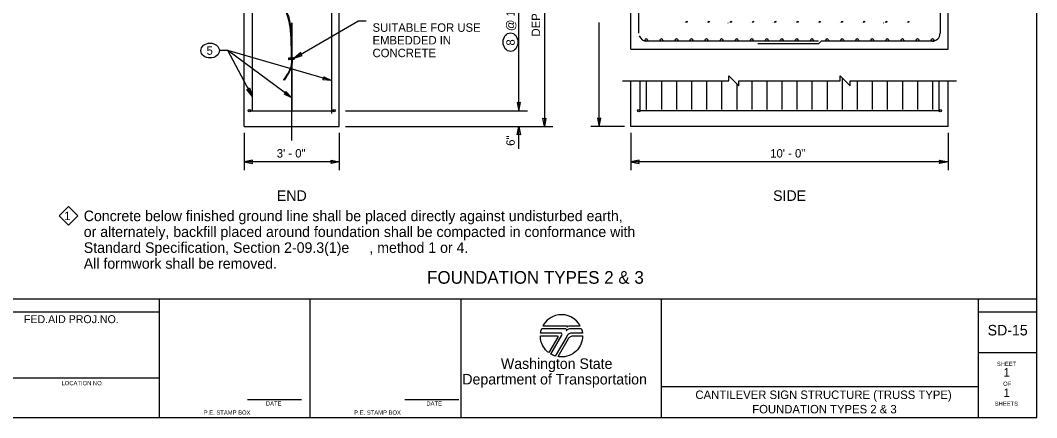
# Model space of a CAD drawing. Extents: x 99862 to 103151, y 100000 to 102076.
# Drawn here: x 101227 to 103150, y 100000 to 100752 of the extents above; entities that cross this region are included whole.
import ezdxf

# ---------------------------------------------------------------- set-up
doc = ezdxf.new("R2010")
doc.units = 0
for name, color, linetype in [('Level 10', 7, 'Continuous'), ('Level 12', 7, 'Continuous'), ('Level 15', 7, 'Continuous'), ('Level 2', 7, 'Continuous'), ('Level 20', 7, 'Continuous'), ('Level 23', 7, 'Continuous'), ('Level 60', 7, 'Continuous'), ('Level 62', 7, 'Continuous'), ('Level 7', 7, 'Continuous')]:
    doc.layers.add(name, color=color, linetype=linetype)

msp = doc.modelspace()

# ---------------------------------------------------------------- linework, layer by layer
at = {"layer": 'Level 10'}
for p, q in [((101665.3, 101195.7), (101665.3, 100580.7)), ((101665.3, 101195.7), (101665.3, 100580.7)), ((101815.3, 101195.7), (101815.3, 100575.4)), ((102397.2, 100727), (102397.2, 100847)), ((102967.2, 100847), (102967.2, 100727)), ((101740.3, 100747.1), (101740.3, 100700.8)), ((101740.3, 100747.1), (101740.3, 100700.8)), ((102737.2, 100712), (102412.2, 100712)), ((102737.2, 100707), (102622.2, 100707)), ((102742.2, 100712), (102737.2, 100707)), ((102952.2, 100712), (102742.2, 100712)), ((101740.3, 100667.4), (101740.3, 100580.7)), ((101740.3, 100667.4), (101740.3, 100580.7)), ((102399.4, 100583.2), (102399.4, 100637)), ((102399.4, 100583.2), (102399.4, 100637)), ((102411.3, 100637), (102411.3, 100583.2)), ((102411.3, 100637), (102411.3, 100583.2)), ((102439.8, 100637), (102439.8, 100583.2)), ((102439.8, 100637), (102439.8, 100583.2)), ((102468.3, 100637), (102468.3, 100583.2)), ((102468.3, 100637), (102468.3, 100583.2)), ((102496.8, 100637), (102496.8, 100583.2)), ((102496.8, 100637), (102496.8, 100583.2)), ((102525.3, 100637), (102525.3, 100583.2)), ((102525.3, 100637), (102525.3, 100583.2)), ((102553.8, 100637), (102553.8, 100583.2)), ((102553.8, 100637), (102553.8, 100583.2)), ((102582.3, 100631.5), (102582.3, 100583.2)), ((102582.3, 100631.5), (102582.3, 100583.2)), ((102610.8, 100637), (102610.8, 100583.2)), ((102610.8, 100637), (102610.8, 100583.2)), ((102639.3, 100637), (102639.3, 100583.2)), ((102639.3, 100637), (102639.3, 100583.2)), ((102667.8, 100637), (102667.8, 100583.2)), ((102667.8, 100637), (102667.8, 100583.2)), ((102696.3, 100637), (102696.3, 100583.2)), ((102696.3, 100637), (102696.3, 100583.2)), ((102724.8, 100637), (102724.8, 100583.2)), ((102724.8, 100637), (102724.8, 100583.2)), ((102753.3, 100637), (102753.3, 100583.2)), ((102753.3, 100637), (102753.3, 100583.2)), ((102781.8, 100642.7), (102781.8, 100583.2)), ((102781.8, 100642.7), (102781.8, 100583.2)), ((102810.3, 100637), (102810.3, 100583.2)), ((102810.3, 100637), (102810.3, 100583.2)), ((102838.8, 100637), (102838.8, 100583.2)), ((102838.8, 100637), (102838.8, 100583.2)), ((102867.3, 100637), (102867.3, 100583.2)), ((102867.3, 100637), (102867.3, 100583.2)), ((102895.8, 100637), (102895.8, 100583.2)), ((102895.8, 100637), (102895.8, 100583.2)), ((102924.3, 100637), (102924.3, 100583.2)), ((102924.3, 100637), (102924.3, 100583.2)), ((102952.8, 100637), (102952.8, 100583.2)), ((102952.8, 100637), (102952.8, 100583.2)), ((102965, 100637), (102965, 100583.2)), ((101660.3, 100580.7), (101820.3, 100580.7)), ((101660.3, 100580.7), (101820.3, 100580.7)), ((102967.2, 100580.7), (102397.2, 100580.7))]:
    msp.add_line(p, q, dxfattribs=at)
for centre in [(102411.3, 100714.5), (102411.3, 100714.5), (102439.8, 100714.5), (102439.8, 100714.5), (102468.3, 100714.5), (102468.3, 100714.5), (102496.8, 100714.5), (102496.8, 100714.5), (102525.3, 100714.5), (102525.3, 100714.5), (102553.8, 100714.5), (102553.8, 100714.5), (102582.3, 100714.5), (102582.3, 100714.5), (102610.8, 100714.5), (102610.8, 100714.5), (102639.3, 100714.5), (102639.3, 100714.5), (102667.8, 100714.5), (102667.8, 100714.5), (102696.3, 100714.5), (102696.3, 100714.5), (102724.8, 100714.5), (102724.8, 100714.5), (102753.3, 100714.5), (102753.3, 100714.5), (102781.8, 100714.5), (102781.8, 100714.5), (102810.3, 100714.5), (102810.3, 100714.5), (102838.8, 100714.5), (102838.8, 100714.5), (102867.3, 100714.5), (102867.3, 100714.5), (102895.8, 100714.5), (102895.8, 100714.5), (102924.3, 100714.5), (102924.3, 100714.5), (102952.8, 100714.5), (102952.8, 100714.5), (101660.3, 100580.7), (101660.3, 100580.7), (101820.3, 100580.7), (101820.3, 100580.7), (102397.2, 100580.7), (102397.2, 100580.7), (102967.2, 100580.7), (102967.2, 100580.7)]:
    msp.add_circle(centre, 2.5, dxfattribs=at)
for centre, start, end in [((102952.2, 100727), 270, 0), ((102412.2, 100727), 197.2697, 270.4082)]:
    msp.add_arc(centre, 15, start, end, dxfattribs=at)
at = {"layer": 'Level 12'}
for p, q in [((101736, 100751.4), (101735, 100750)), ((101736, 100751.4), (101735, 100750)), ((101735.6, 100746.8), (101736.7, 100748.1)), ((101735.6, 100746.8), (101736.7, 100748.1)), ((101738.8, 100731.7), (101737.6, 100730.5)), ((101738.8, 100731.7), (101737.6, 100730.5)), ((101737.8, 100727.2), (101739, 100728.4)), ((101737.8, 100727.2), (101739, 100728.4)), ((101739.9, 100713.4), (101738.6, 100712.2)), ((101739.9, 100713.4), (101738.6, 100712.2)), ((101738.7, 100708.9), (101740, 100710)), ((101738.7, 100708.9), (101740, 100710)), ((101740.5, 100692.5), (101739.2, 100691.4)), ((101740.5, 100692.5), (101739.2, 100691.4)), ((101739.3, 100688.1), (101740.6, 100689.2)), ((101739.3, 100688.1), (101740.6, 100689.2)), ((101735.8, 100658), (101737.4, 100658.5)), ((101735.8, 100658), (101737.4, 100658.5)), ((101738.6, 100661.6), (101737, 100661)), ((101738.6, 100661.6), (101737, 100661)), ((101726.4, 100641.6), (101728.1, 100641.9)), ((101726.4, 100641.6), (101728.1, 100641.9)), ((101730, 100644.6), (101728.3, 100644.4)), ((101730, 100644.6), (101728.3, 100644.4))]:
    msp.add_line(p, q, dxfattribs=at)
for points in [[(101736, 100751.4), (101736, 100751.4)], [(101736, 100751.4), (101736, 100751.4)], [(101736.7, 100748.1), (101736.7, 100748.1)], [(101736.7, 100748.1), (101736.7, 100748.1)], [(101738.8, 100731.7), (101738.8, 100731.7)], [(101738.8, 100731.7), (101738.8, 100731.7)], [(101739, 100728.4), (101739, 100728.4)], [(101739, 100728.4), (101739, 100728.4)], [(101739.9, 100713.4), (101739.9, 100713.4)], [(101739.9, 100713.4), (101739.9, 100713.4)], [(101740, 100710), (101740, 100710)], [(101740, 100710), (101740, 100710)], [(101740.5, 100692.5), (101740.5, 100692.5)], [(101740.5, 100692.5), (101740.5, 100692.5)], [(101740.6, 100689.2), (101740.6, 100689.2)], [(101740.6, 100689.2), (101740.6, 100689.2)], [(101737.4, 100658.5), (101737.4, 100658.5)], [(101737.4, 100658.5), (101737.4, 100658.5)], [(101738.6, 100661.6), (101738.6, 100661.6)], [(101738.6, 100661.6), (101738.6, 100661.6)], [(101728.1, 100641.9), (101728.1, 100641.9)], [(101728.1, 100641.9), (101728.1, 100641.9)], [(101730, 100644.6), (101730, 100644.6)], [(101730, 100644.6), (101730, 100644.6)]]:
    msp.add_lwpolyline(points, dxfattribs=at)
for points in [[(101735, 100750), (101735.2, 100748.9), (101735.4, 100747.8), (101735.6, 100746.8)], [(101735, 100750), (101735.2, 100748.9), (101735.4, 100747.8), (101735.6, 100746.8)], [(101736.7, 100748.1), (101736.4, 100749.2), (101736.2, 100750.3), (101736, 100751.4)], [(101736.7, 100748.1), (101736.4, 100749.2), (101736.2, 100750.3), (101736, 100751.4)], [(101737.6, 100730.5), (101737.6, 100729.4), (101737.7, 100728.3), (101737.8, 100727.2)], [(101737.6, 100730.5), (101737.6, 100729.4), (101737.7, 100728.3), (101737.8, 100727.2)], [(101739, 100728.4), (101738.9, 100729.5), (101738.8, 100730.6), (101738.8, 100731.7)], [(101739, 100728.4), (101738.9, 100729.5), (101738.8, 100730.6), (101738.8, 100731.7)], [(101738.6, 100712.2), (101738.7, 100711.1), (101738.7, 100710), (101738.7, 100708.9)], [(101738.6, 100712.2), (101738.7, 100711.1), (101738.7, 100710), (101738.7, 100708.9)], [(101740, 100710), (101739.9, 100711.1), (101739.9, 100712.2), (101739.9, 100713.4)], [(101740, 100710), (101739.9, 100711.1), (101739.9, 100712.2), (101739.9, 100713.4)], [(101739.2, 100691.4), (101739.3, 100690.3), (101739.3, 100689.2), (101739.3, 100688.1)], [(101739.2, 100691.4), (101739.3, 100690.3), (101739.3, 100689.2), (101739.3, 100688.1)], [(101740.6, 100689.2), (101740.5, 100690.3), (101740.5, 100691.4), (101740.5, 100692.5)], [(101740.6, 100689.2), (101740.5, 100690.3), (101740.5, 100691.4), (101740.5, 100692.5)], [(101737, 100661), (101736.6, 100660), (101736.2, 100659), (101735.8, 100658)], [(101737, 100661), (101736.6, 100660), (101736.2, 100659), (101735.8, 100658)], [(101737.4, 100658.5), (101737.8, 100659.6), (101738.2, 100660.6), (101738.6, 100661.6)], [(101737.4, 100658.5), (101737.8, 100659.6), (101738.2, 100660.6), (101738.6, 100661.6)], [(101728.3, 100644.4), (101727.7, 100643.5), (101727.1, 100642.6), (101726.4, 100641.6)], [(101728.3, 100644.4), (101727.7, 100643.5), (101727.1, 100642.6), (101726.4, 100641.6)], [(101728.1, 100641.9), (101728.7, 100642.8), (101729.4, 100643.7), (101730, 100644.6)], [(101728.1, 100641.9), (101728.7, 100642.8), (101729.4, 100643.7), (101730, 100644.6)]]:
    msp.add_open_spline(points, degree=2, dxfattribs=at)
at = {"layer": 'Level 15'}
for p, q in [((102218.3, 101150.7), (102218.3, 100550.7)), ((102218.3, 101150.7), (102218.3, 100550.7)), ((102170.3, 100580.7), (102170.3, 101110.7)), ((102170.3, 100580.7), (102170.3, 101110.7)), ((101740.3, 100667.4), (101740.3, 100747.1)), ((101740.3, 100667.4), (101740.3, 100747.1)), ((101745.1, 100680), (101865.2, 100749.9)), ((101881.2, 100749.9), (101865.2, 100749.9)), ((101881.2, 100749.9), (101865.2, 100749.9)), ((102322.2, 100550.7), (102322.2, 100747.7)), ((101619.3, 100694.4), (101603.3, 100694.4)), ((101619.3, 100694.4), (101603.3, 100694.4)), ((101665.3, 100608.4), (101619.3, 100694.4)), ((101740.3, 100605.2), (101619.3, 100694.4)), ((101815.3, 100637.6), (101619.3, 100694.4)), ((101665.3, 100608.4), (101619.3, 100694.4)), ((101740.3, 100605.2), (101619.3, 100694.4)), ((101740.3, 100524), (101740.3, 100667.4)), ((101740.3, 100524), (101740.3, 100667.4)), ((102366.2, 100637), (102567.5, 100637)), ((102567.5, 100637), (102567.5, 100646.3)), ((102567.5, 100646.3), (102586.1, 100627.7)), ((102567.5, 100637), (102567.5, 100646.3)), ((102567.5, 100646.3), (102586.1, 100627.7)), ((102586.1, 100627.7), (102586.1, 100637)), ((102586.1, 100637), (102778.2, 100637)), ((102586.1, 100627.7), (102586.1, 100637)), ((102586.1, 100637), (102778.2, 100637)), ((102778.2, 100637), (102778.2, 100646.3)), ((102778.2, 100646.3), (102796.8, 100627.7)), ((102778.2, 100637), (102778.2, 100646.3)), ((102778.2, 100646.3), (102796.8, 100627.7)), ((102796.8, 100627.7), (102796.8, 100637)), ((102796.8, 100637), (102998.2, 100637)), ((102796.8, 100627.7), (102796.8, 100637)), ((101842.3, 100580.7), (102186.3, 100580.7)), ((101842.3, 100580.7), (102186.3, 100580.7)), ((101650.3, 100538.7), (101650.3, 100468)), ((101650.3, 100538.7), (101650.3, 100468)), ((101830.3, 100538.7), (101830.3, 100468)), ((101830.3, 100538.7), (101830.3, 100468)), ((101842.3, 100550.7), (102234.3, 100550.7)), ((101842.3, 100550.7), (102234.3, 100550.7)), ((102170.3, 100508.6), (102170.3, 100550.7)), ((102170.3, 100508.6), (102170.3, 100550.7)), ((102370.2, 100550.7), (102306.2, 100550.7)), ((102382.2, 100538.7), (102382.2, 100468)), ((102982.2, 100538.7), (102982.2, 100468)), ((101830.3, 100484), (101650.3, 100484)), ((101830.3, 100484), (101650.3, 100484)), ((102982.2, 100484), (102382.2, 100484)), ((102982.2, 100484), (102382.2, 100484))]:
    msp.add_line(p, q, dxfattribs=at)
for points in [[(101745.1, 100680), (101760.3, 100685.2), (101758.1, 100687.5), (101757.2, 100690.6)], [(101815.3, 100637.6), (101799.3, 100639.1), (101800.9, 100641.9), (101801.1, 100645)], [(101665.3, 100608.4), (101655.1, 100620.8), (101658.2, 100621.6), (101660.6, 100623.7)], [(101740.3, 100605.2), (101725.8, 100612), (101728.2, 100614), (101729.4, 100617)], [(102170.3, 100580.7), (102173.4, 100596.4), (102170.3, 100595.7), (102167.2, 100596.4)], [(102170.3, 100580.7), (102173.4, 100596.4), (102170.3, 100595.7), (102167.2, 100596.4)], [(102218.3, 100550.7), (102215.2, 100566.4), (102218.3, 100565.7), (102221.4, 100566.4)], [(102218.3, 100550.7), (102215.2, 100566.4), (102218.3, 100565.7), (102221.4, 100566.4)], [(102322.2, 100550.7), (102325.3, 100566.4), (102322.2, 100565.7), (102319.1, 100566.4)], [(102170.3, 100550.7), (102173.4, 100535), (102170.3, 100535.7), (102167.2, 100535)], [(102170.3, 100550.7), (102173.4, 100535), (102170.3, 100535.7), (102167.2, 100535)], [(101650.3, 100484), (101666, 100481), (101665.3, 100484), (101666, 100487.1)], [(101650.3, 100484), (101666, 100481), (101665.3, 100484), (101666, 100487.1)], [(101830.3, 100484), (101814.6, 100481), (101815.3, 100484), (101814.6, 100487.1)], [(101830.3, 100484), (101814.6, 100481), (101815.3, 100484), (101814.6, 100487.1)], [(102382.2, 100484), (102397.9, 100481), (102397.2, 100484), (102397.9, 100487.1)], [(102382.2, 100484), (102397.9, 100481), (102397.2, 100484), (102397.9, 100487.1)], [(102982.2, 100484), (102966.4, 100481), (102967.2, 100484), (102966.4, 100487.1)], [(102982.2, 100484), (102966.4, 100481), (102967.2, 100484), (102966.4, 100487.1)]]:
    msp.add_lwpolyline(points, close=True, dxfattribs=at)
at = {"layer": 'Level 2'}
for p, q in [((101650.3, 100550.7), (101650.3, 101008.6)), ((101830.3, 100550.7), (101830.3, 101008.6)), ((101830.3, 100550.7), (101830.3, 101008.6)), ((102382.2, 100697), (102382.2, 100877)), ((102382.2, 100697), (102382.2, 100877)), ((102982.2, 100697), (102982.2, 100877)), ((102982.2, 100697), (102982.2, 100877)), ((102382.2, 100697), (102982.2, 100697)), ((102382.2, 100697), (102982.2, 100697)), ((102382.2, 100550.7), (102382.2, 100637)), ((102982.2, 100550.7), (102982.2, 100637)), ((101650.3, 100550.7), (101830.3, 100550.7)), ((101650.3, 100550.7), (101830.3, 100550.7)), ((102982.2, 100550.7), (102382.2, 100550.7))]:
    msp.add_line(p, q, dxfattribs=at)
at = {"layer": 'Level 20'}
msp.add_lwpolyline([(101317.9, 100399.2), (101335.5, 100381.7), (101317.9, 100364.1), (101300.4, 100381.7)], close=True, dxfattribs=at)
msp.add_lwpolyline([(101317.9, 100399.2), (101335.5, 100381.7), (101317.9, 100364.1), (101300.4, 100381.7)], close=True, dxfattribs=at)
for centre, major_axis in [((102154.3, 100710.3), (0, -17.5)), ((101585.8, 100694.4), (-17.5, 0))]:
    msp.add_ellipse(centre, major_axis=major_axis, ratio=0.8, dxfattribs=at)
at = {"layer": 'Level 23'}
for p, q in [((102481.8, 100747), (102481.9, 100746.9)), ((102481.8, 100747), (102481.9, 100746.9)), ((102523.8, 100747), (102523.9, 100746.9)), ((102523.8, 100747), (102523.9, 100746.9)), ((102565.8, 100747), (102565.9, 100746.9)), ((102565.8, 100747), (102565.9, 100746.9)), ((102607.8, 100747), (102607.9, 100746.9)), ((102607.8, 100747), (102607.9, 100746.9)), ((102649.8, 100747), (102649.9, 100746.9)), ((102649.8, 100747), (102649.9, 100746.9)), ((102691.8, 100747), (102691.9, 100746.9)), ((102691.8, 100747), (102691.9, 100746.9)), ((102733.8, 100747), (102733.9, 100746.9)), ((102733.8, 100747), (102733.9, 100746.9)), ((102775.8, 100747), (102775.9, 100746.9)), ((102775.8, 100747), (102775.9, 100746.9)), ((102817.8, 100747), (102817.9, 100746.9)), ((102817.8, 100747), (102817.9, 100746.9)), ((102859.8, 100747), (102859.9, 100746.9)), ((102859.8, 100747), (102859.9, 100746.9)), ((102901.8, 100747), (102901.9, 100746.9)), ((102901.8, 100747), (102901.9, 100746.9))]:
    msp.add_line(p, q, dxfattribs=at)
for points in [[(102486.1, 100747.7), (102487.2, 100750), (102489, 100748.6), (102486.1, 100747.7)], [(102486.1, 100747.7), (102487.2, 100750), (102489, 100748.6), (102486.1, 100747.7)], [(102528.1, 100747.7), (102529.2, 100750), (102531, 100748.6), (102528.1, 100747.7)], [(102528.1, 100747.7), (102529.2, 100750), (102531, 100748.6), (102528.1, 100747.7)], [(102570.1, 100747.7), (102571.2, 100750), (102573, 100748.6), (102570.1, 100747.7)], [(102570.1, 100747.7), (102571.2, 100750), (102573, 100748.6), (102570.1, 100747.7)], [(102612.1, 100747.7), (102613.2, 100750), (102615, 100748.6), (102612.1, 100747.7)], [(102612.1, 100747.7), (102613.2, 100750), (102615, 100748.6), (102612.1, 100747.7)], [(102654.1, 100747.7), (102655.2, 100750), (102657, 100748.6), (102654.1, 100747.7)], [(102654.1, 100747.7), (102655.2, 100750), (102657, 100748.6), (102654.1, 100747.7)], [(102696.1, 100747.7), (102697.2, 100750), (102699, 100748.6), (102696.1, 100747.7)], [(102696.1, 100747.7), (102697.2, 100750), (102699, 100748.6), (102696.1, 100747.7)], [(102738.1, 100747.7), (102739.2, 100750), (102741, 100748.6), (102738.1, 100747.7)], [(102738.1, 100747.7), (102739.2, 100750), (102741, 100748.6), (102738.1, 100747.7)], [(102780.1, 100747.7), (102781.2, 100750), (102783, 100748.6), (102780.1, 100747.7)], [(102780.1, 100747.7), (102781.2, 100750), (102783, 100748.6), (102780.1, 100747.7)], [(102822.1, 100747.7), (102823.2, 100750), (102825, 100748.6), (102822.1, 100747.7)], [(102822.1, 100747.7), (102823.2, 100750), (102825, 100748.6), (102822.1, 100747.7)], [(102864.1, 100747.7), (102865.2, 100750), (102867, 100748.6), (102864.1, 100747.7)], [(102864.1, 100747.7), (102865.2, 100750), (102867, 100748.6), (102864.1, 100747.7)], [(102906.1, 100747.7), (102907.2, 100750), (102909, 100748.6), (102906.1, 100747.7)], [(102906.1, 100747.7), (102907.2, 100750), (102909, 100748.6), (102906.1, 100747.7)]]:
    msp.add_lwpolyline(points, dxfattribs=at)
at = {"layer": 'Level 60'}
for p, q in [((103150, 100000), (103150, 102075)), ((100000, 100225), (103150, 100225)), ((101490.1, 100000), (101490.1, 100225)), ((101775.1, 100000), (101775.1, 100225)), ((102060.1, 100225), (102060.1, 100000)), ((102439.1, 100225), (102439.1, 100000)), ((103039.1, 100225), (103039.1, 100000)), ((100000, 100200), (101490.1, 100200)), ((103039.1, 100200), (103150, 100200)), ((103039.1, 100123.4), (103150, 100123.4)), ((101490.1, 100075), (101088.5, 100075)), ((102439.1, 100059.1), (103039.1, 100059.1)), ((101656.7, 100034.6), (101759, 100034.6)), ((101954.4, 100034.6), (102056.6, 100034.6)), ((100000, 100000), (103150, 100000))]:
    msp.add_line(p, q, dxfattribs=at)
for points in [[(102215.6, 100173.9), (102259.9, 100173.9), (102260.7, 100173.7), (102261.4, 100173.2), (102261.7, 100172.6), (102261.7, 100172), (102261.5, 100171.2), (102262.3, 100172.2), (102263.5, 100173.1), (102265.2, 100173.8), (102266.4, 100173.9), (102285.9, 100173.9), (102283, 100178.5), (102278.9, 100183.3), (102273.7, 100187.6), (102268.3, 100190.8), (102263.3, 100192.8), (102257.6, 100194.2), (102251.6, 100194.8), (102245.1, 100194.4), (102239.7, 100193.3), (102235.1, 100191.6), (102231.1, 100189.6), (102227.3, 100187.2), (102223.7, 100184.3), (102219.8, 100180.1), (102217.5, 100176.9)], [(102215.6, 100173.9), (102259.9, 100173.9), (102260.7, 100173.7), (102261.4, 100173.2), (102261.7, 100172.6), (102261.7, 100172), (102261.5, 100171.2), (102262.3, 100172.2), (102263.5, 100173.1), (102265.2, 100173.8), (102266.4, 100173.9), (102285.9, 100173.9), (102283, 100178.5), (102278.9, 100183.3), (102273.7, 100187.6), (102268.3, 100190.8), (102263.3, 100192.8), (102257.6, 100194.2), (102251.6, 100194.8), (102245.1, 100194.4), (102239.7, 100193.3), (102235.1, 100191.6), (102231.1, 100189.6), (102227.3, 100187.2), (102223.7, 100184.3), (102219.8, 100180.1), (102217.5, 100176.9)], [(102213.3, 100168.7), (102257.2, 100168.7), (102257.9, 100168.6), (102258.5, 100168.4), (102258.9, 100168.2), (102259.2, 100167.9), (102259.7, 100167.3), (102260, 100166.6), (102260.2, 100165.9), (102260.1, 100165.2), (102260, 100164.7), (102259.7, 100164.2), (102260.2, 100164.9), (102261.1, 100165.9), (102262.1, 100166.8), (102263.4, 100167.6), (102264.6, 100168.1), (102266.5, 100168.6), (102269.2, 100168.7), (102288.3, 100168.7), (102289.1, 100166.2), (102289.6, 100164.5), (102290, 100162.7), (102290.3, 100160.9), (102290.4, 100160.1), (102272, 100160.1), (102269.5, 100160), (102267.7, 100159.7), (102265.2, 100158.7), (102263.2, 100157.2), (102261.8, 100155.7), (102260.6, 100153.7), (102239.1, 100116.6), (102236.5, 100117.5), (102234.2, 100118.5), (102232.2, 100119.5), (102230.7, 100120.3), (102251.5, 100156.1), (102251.9, 100157.4), (102251.6, 100158.6), (102250.7, 100159.6), (102249.9, 100160), (102249.3, 100160.1), (102211.2, 100160.1), (102211.6, 100162.6), (102211.8, 100163.9), (102212.2, 100165.3), (102212.7, 100167)], [(102210.8, 100154.8), (102242.3, 100154.8), (102242.7, 100154.8), (102243.2, 100154.6), (102243.5, 100154.4), (102243.7, 100154.1), (102243.9, 100153.7), (102243.9, 100153.3), (102243.9, 100152.9), (102243.7, 100152.4), (102226.6, 100123), (102224.5, 100124.7), (102222.6, 100126.5), (102220.7, 100128.5), (102218.3, 100131.5), (102216.6, 100134.1), (102215, 100137), (102213.6, 100140.2), (102212.6, 100143), (102211.8, 100146), (102211.2, 100149), (102210.9, 100152)], [(102244.2, 100115.4), (102264.2, 100150), (102264.8, 100150.9), (102265.4, 100151.6), (102266.3, 100152.5), (102267.2, 100153.2), (102268.3, 100153.8), (102269.5, 100154.3), (102270.8, 100154.6), (102271.5, 100154.7), (102272.4, 100154.7), (102290.8, 100154.7), (102290.5, 100150.3), (102290, 100146.9), (102288.8, 100142.5), (102287.6, 100139.3), (102286, 100135.9), (102283.5, 100131.9), (102280.8, 100128.4), (102278.9, 100126.4), (102276.1, 100123.9), (102272.7, 100121.4), (102268.7, 100119.1), (102265, 100117.5), (102260.9, 100116.2), (102256.9, 100115.3), (102252.4, 100114.9), (102249.2, 100114.9), (102246.3, 100115.1)]]:
    msp.add_lwpolyline(points, close=True, dxfattribs=at)
at = {"layer": 'Level 7'}
for p, q in [((101735.6, 100680.4), (101743.7, 100680.5)), ((101743.7, 100677.7), (101735.7, 100677.6)), ((101725, 100639.4), (101726, 100638.7)), ((101725, 100639.4), (101726, 100638.7))]:
    msp.add_line(p, q, dxfattribs=at)
for centre, start, end in [((101735.4, 100679), 81.3704, 279.6951), ((101743.9, 100679.1), 261.3704, 99.6951)]:
    msp.add_arc(centre, 1.41, start, end, dxfattribs=at)
for points, degree in [([(101688.9, 100880.5), (101691.2, 100819.8), (101733.3, 100769.7), (101738.2, 100745.8), (101739.8, 100672.8)], 3), ([(101690.1, 100880.6), (101691.3, 100850.8), (101697, 100829.7), (101707.4, 100805.6), (101711.1, 100798.8), (101718.4, 100787), (101721.9, 100781.9), (101727.9, 100772.5), (101730.3, 100768.3), (101734.3, 100758.8), (101735.7, 100753.6), (101739.2, 100733.9), (101740.1, 100715.4), (101741.1, 100673.2)], 3), ([(101739.8, 100672.8), (101739.2, 100664.7), (101735.8, 100655.1), (101725, 100639.4)], 2), ([(101739.8, 100672.8), (101739.2, 100664.7), (101735.8, 100655.1), (101725, 100639.4)], 2), ([(101741.1, 100673.2), (101741, 100671.5), (101740.8, 100669.6), (101739.8, 100665.3), (101739.1, 100662.6), (101735.6, 100654), (101731.9, 100647.2), (101726, 100638.7)], 3), ([(101741.1, 100673.2), (101741, 100671.5), (101740.8, 100669.6), (101739.8, 100665.3), (101739.1, 100662.6), (101735.6, 100654), (101731.9, 100647.2), (101726, 100638.7)], 3)]:
    msp.add_open_spline(points, degree=degree, dxfattribs=at)

# ---------------------------------------------------------------- texts
at = {"layer": 'Level 20'}
for s, rotation, p in [('     @ 1\' - 6" MAX. SPACING', 90, (102162.3, 100701.5)), ('DEPTH =', 90, (102210.3, 100721)), ('SUITABLE FOR USE', 360, (101893.2, 100729.9)), ('EMBEDDED IN ', 360, (101893.2, 100705.9)), ('8', 90, (102162.3, 100703.8)), ('CONCRETE', 360, (101893.2, 100681.9)), ('6"', 90, (102162.3, 100514.2)), ('6"', 90, (102162.3, 100514.2))]:
    msp.add_text(s, height=16, rotation=rotation, dxfattribs=at).set_placement(p)
for s, height, p in [('5', 16, (101579, 100686.4)), ('3\' - 0"', 16, (101711.9, 100492)), ('3\' - 0"', 16, (101711.9, 100492)), ('10\' - 0"', 16, (102645.8, 100492)), ('END', 20, (101712.2, 100410)), ('END', 20, (101712.2, 100410)), ('SIDE', 20, (102651.2, 100410)), ('1', 16, (101309.8, 100373.7)), ('1', 16, (101309.8, 100373.7)), ('Concrete below finished ground line shall be placed directly against undisturbed earth, ', 20, (101346.7, 100371.7)), ('or alternately, backfill placed around foundation shall be compacted in conformance with', 20, (101346.7, 100341.7)), ('Standard Specification, Section 2-09.3(1)e', 20, (101346.7, 100311.7)), (', method 1 or 4. ', 20, (101887.2, 100311.7)), ('All formwork shall be removed.', 20, (101346.7, 100281.7)), ('FOUNDATION TYPES 2 & 3', 24, (101996.4, 100253.3)), ('1', 16, (103087.1, 100077.7)), ('CANTILEVER SIGN STRUCTURE (TRUSS TYPE)', 16, (102504.2, 100035.3)), ('1', 16, (103087.1, 100039.1)), ('FOUNDATION TYPES 2 & 3', 16, (102611.7, 100008.1))]:
    msp.add_text(s, height=height, dxfattribs=at).set_placement(p)
at = {"layer": 'Level 60'}
for s, height, p in [('FED.AID PROJ.NO.', 15, (101233.5, 100178.8)), ('Washington State', 19.999, (102136.1, 100092.2)), ('SHEET', 8, (103074.6, 100097.8)), ('Department of Transportation', 19.999, (102063.1, 100062.8)), ('LOCATION NO.', 8, (101304.6, 100061.3)), ('OF', 8, (103086.6, 100060.1)), ('P.E. STAMP BOX', 8, (101573.8, 100005.7)), ('DATE', 8.03, (101691.4, 100022.8)), ('P.E. STAMP BOX', 8, (101858.4, 100005.7)), ('DATE', 8.03, (101995.1, 100022.8)), ('SHEETS', 8, (103070.6, 100022.4))]:
    msp.add_text(s, height=height, dxfattribs=at).set_placement(p)
at = {"layer": 'Level 62'}
msp.add_text('SD-15', height=20, dxfattribs=at).set_placement((103057.2, 100155.5))

doc.saveas('drawing.dxf')
